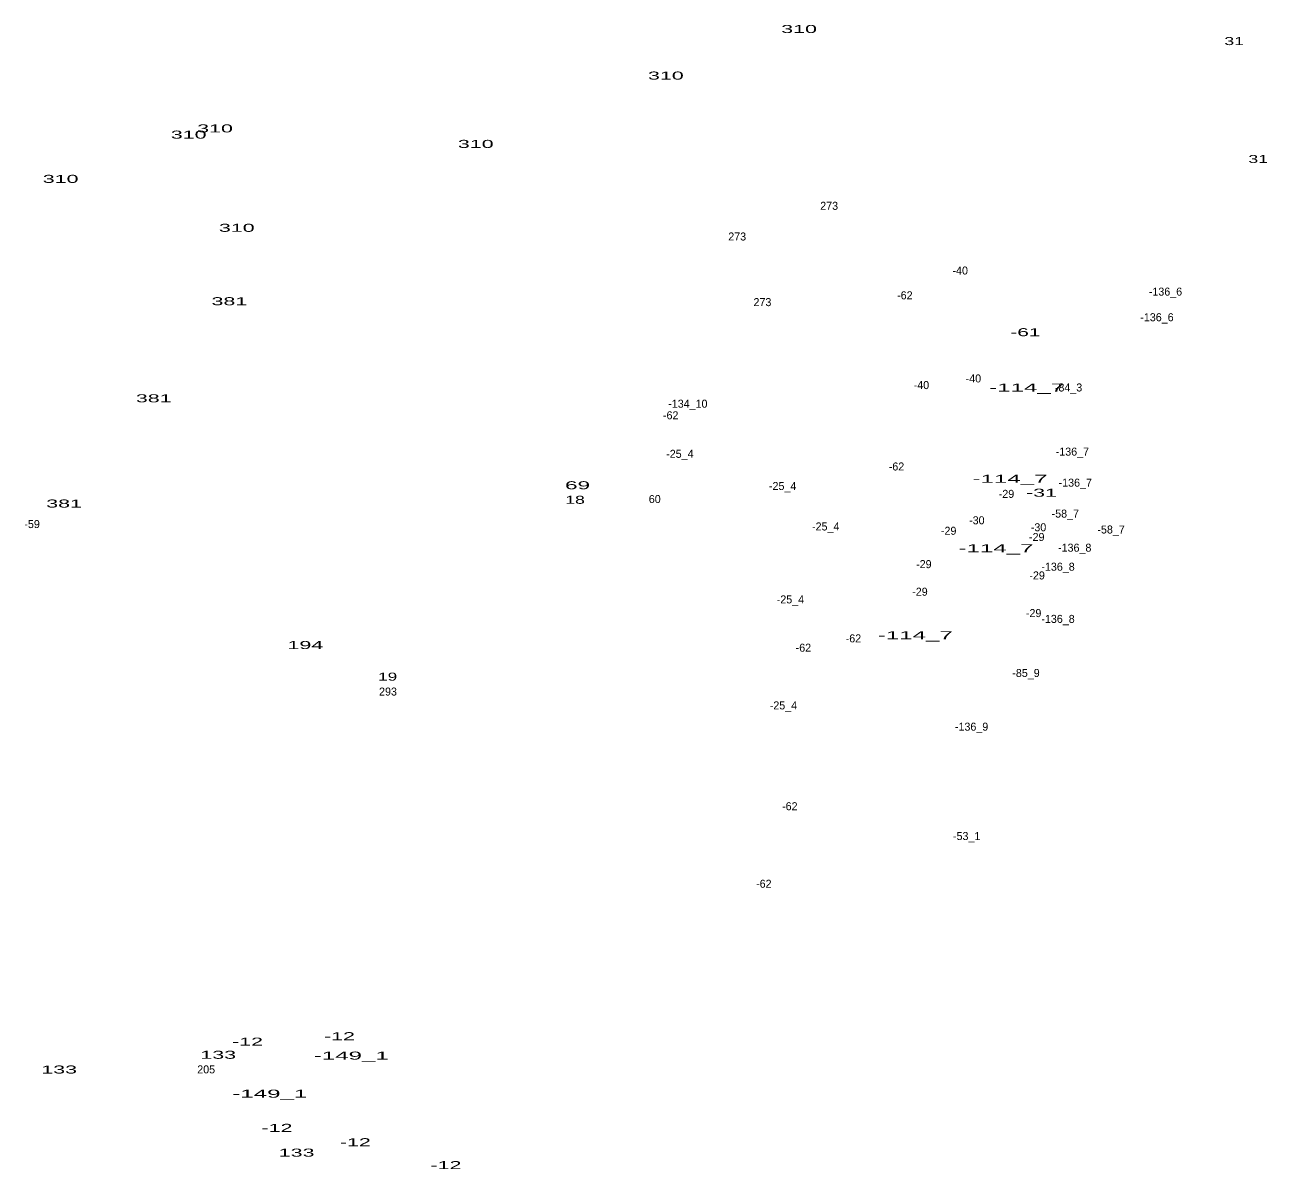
# Model space of a CAD drawing. Extents: x -662499 to -659675, y -1001682 to -998165.
# Drawn here: x -660422 to -659801, y -1000540 to -999969 of the extents above; entities that cross this region are included whole.
import ezdxf
from ezdxf.enums import TextEntityAlignment as Align

# ---------------------------------------------------------------- set-up
doc = ezdxf.new("R2010")
doc.units = 0
doc.header["$LTSCALE"] = 1.6
doc.layers.add('24', color=7, linetype='Continuous')

msp = doc.modelspace()

# ---------------------------------------------------------------- texts
at = {"layer": '24'}
for s, width, p in [('310', 2, (-660034.864, -999972.69)), ('31', 1.65, (-659817.447, -999978.73)), ('310', 2, (-660101.434, -999995.96)), ('310', 2, (-660326.714, -1000022.34)), ('310', 2, (-660339.894, -1000025.44)), ('310', 2, (-660196.434, -1000030.09)), ('31', 1.65, (-659805.437, -1000037.62)), ('310', 2, (-660403.874, -1000047.55)), ('310', 2, (-660315.854, -1000071.98)), ('381', 2, (-660319.547, -1000108.65)), ('-61', 1.95, (-659921.755, -1000124.12)), ('-114_7', 2.25, (-659921.118, -1000151.75)), ('381', 2, (-660357.347, -1000157.13)), ('69', 2.1, (-660145.561, -1000200.56)), ('-114_7', 2.25, (-659929.458, -1000197.32)), ('18', 1.65, (-660146.817, -1000207.82)), ('-31', 2, (-659913.731, -1000204.28)), ('381', 2, (-660402.137, -1000209.69)), ('-114_7', 2.25, (-659936.438, -1000231.99)), ('-114_7', 2.25, (-659976.758, -1000275.44)), ('194', 2, (-660281.588, -1000280.36)), ('19', 1.6, (-660240.443, -1000296.15)), ('-12', 2, (-660264.531, -1000475.71)), ('-12', 2, (-660310.481, -1000478.43)), ('133', 2, (-660325.117, -1000484.98)), ('-149_1', 2.25, (-660258.638, -1000485.4)), ('133', 2, (-660404.597, -1000492.35)), ('-149_1', 2.25, (-660299.348, -1000504.41)), ('-12', 2, (-660295.751, -1000521.48)), ('-12', 2, (-660256.591, -1000528.66)), ('133', 2, (-660285.947, -1000533.85)), ('-12', 2, (-660211.321, -1000540.1))]:
    msp.add_text(s, height=4, dxfattribs=dict(at, width=width)).set_placement(p, align=Align.CENTER)
for s, p in [('273', (-660019.833, -1000061)), ('273', (-660065.783, -1000076.32)), ('-40', (-659954.343, -1000093.31)), ('-136_6', (-659851.767, -1000103.85)), ('273', (-660053.173, -1000109.1)), ('-62', (-659982.01, -1000105.69)), ('-136_6', (-659856.027, -1000116.65)), ('-40', (-659947.743, -1000147.22)), ('-40', (-659973.723, -1000150.52)), ('-84_3', (-659900.207, -1000151.72)), ('-62', (-660099.01, -1000165.62)), ('-134_10', (-660090.447, -1000159.83)), ('-136_7', (-659898.297, -1000183.76)), ('-25_4', (-660094.437, -1000184.86)), ('-62', (-659986.18, -1000191.18)), ('-25_4', (-660043.067, -1000200.93)), ('-136_7', (-659896.847, -1000199.27)), ('60', (-660106.987, -1000207.44)), ('-29', (-659931.23, -1000204.86)), ('-58_7', (-659901.828, -1000214.71)), ('-59', (-660418.13, -1000219.94)), ('-25_4', (-660021.547, -1000221.13)), ('-30', (-659946.039, -1000218.05)), ('-30', (-659915.209, -1000221.54)), ('-29', (-659960.11, -1000223.29)), ('-29', (-659916.1, -1000226.39)), ('-58_7', (-659878.948, -1000222.66)), ('-136_8', (-659897.122, -1000231.74)), ('-29', (-659972.52, -1000239.96)), ('-29', (-659915.91, -1000245.59)), ('-136_8', (-659905.462, -1000241.24)), ('-25_4', (-660039.187, -1000257.56)), ('-29', (-659974.46, -1000253.73)), ('-29', (-659917.65, -1000264.4)), ('-136_8', (-659905.462, -1000267.3)), ('-62', (-660007.7, -1000277.03)), ('-62', (-660032.7, -1000281.68)), ('-85_9', (-659921.468, -1000294.31)), ('293', (-660240.293, -1000303.59)), ('-25_4', (-660042.677, -1000310.5)), ('-136_9', (-659948.657, -1000321.13)), ('-62', (-660039.49, -1000360.86)), ('-53_1', (-659951.116, -1000375.75)), ('-62', (-660052.48, -1000399.58)), ('205', (-660331.151, -1000492.28))]:
    msp.add_text(s, height=4, dxfattribs=at).set_placement(p, align=Align.CENTER)

doc.saveas('drawing.dxf')
